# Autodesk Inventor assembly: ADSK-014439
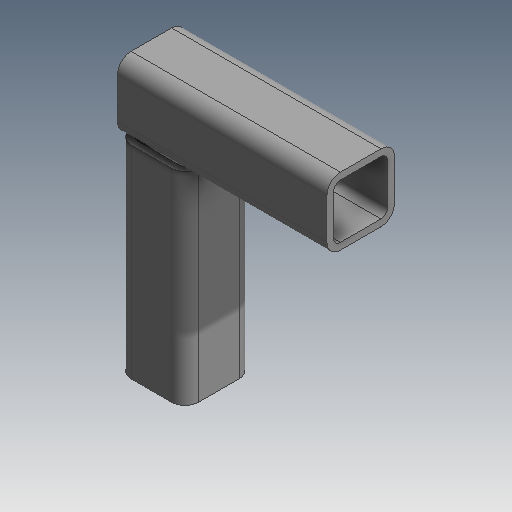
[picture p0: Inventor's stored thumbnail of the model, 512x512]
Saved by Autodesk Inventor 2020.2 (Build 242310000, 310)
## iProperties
Part Number: ADSK-014439
Description: Phantom-Baugruppe
Document SubType Name: Baugruppe
Designer: lutzd
Mass: 316.822 g
Surface Area: 1092.02 cm^2
Volume: 262.757 cm^3
Density: 1.20576 g/cm^3
DocNumber: ADSK-014439
Folder: .
Mass: 0,317 kg
Dimensions: 200x50x155 mm
_FrameDoc: Frame Assembly
_Version: 15.0.0
Title: Gestellbaugruppen
Author: lutzd
Revision Number: -
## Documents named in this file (5)
- D:\07 - DEMODATEN\OTX 2019 - Dataset - UPDATE - Dez2019\Designs\07-Packing machine\500657\Frame\ADSK-014439.iam
- D:\07 - DEMODATEN\OTX 2019 - Dataset - UPDATE - Dez2019\Designs\07-Packing machine\500657\Frame\ADSK-014442.ipt
- D:\07 - DEMODATEN\OTX 2019 - Dataset - UPDATE - Dez2019\Designs\07-Packing machine\500657\Frame\ADSK-014441.ipt
- D:\07 - DEMODATEN\OTX 2019 - Dataset - UPDATE - Dez2019\Designs\07-Packing machine\500657\Frame\ADSK-014440.ipt
- D:\07 - DEMODATEN\OTX 2019 - Dataset - UPDATE - Dez2019\Designs\07-Packing machine\Parts\ADSK-014443.ipt
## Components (4 placed, 3 different names)
1. Gestellreferenzmodell
2. DIN 50 x 50 x 5:1
3. DIN 50 x 50 x 5:2
4. Gerundete Ecken (mm) 5 x 40 x 40:1
